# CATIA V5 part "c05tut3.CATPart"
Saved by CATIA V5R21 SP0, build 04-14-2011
Part number: Part1
Bounding box of the stored display mesh (mm): x -75 to 75, y -150 to 150, z 30 to 180
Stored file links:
  D:\CATIA V5R21 E-RESOURCES\CATIA-V5R21\catia-v5r21-prt\c05-catia-v5r20-prt\catia-v5r21-tut-03.CATPart
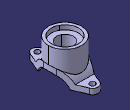
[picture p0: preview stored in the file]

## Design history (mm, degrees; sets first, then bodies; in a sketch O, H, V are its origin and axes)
Body1 (main body)
  Sketch1 on yz-plane, origin (0, 0, 0), H (0, 1, 0), V (0, 0, 1)
    point P1 (0, 42.5)
    line L1 (150, 55) -> (150, 30)
    line L2 (150, 30) -> (74.162, 30)
    line L3 (-150, 30) -> (-150, 55)
    line L4 (-150, 55) -> (-89.4427, 55)
    point P3 (150, 30)
    point P4 (-150, 30)
    arc A1 centre (0, 0) radius 80 from (74.162, 30) to (-74.162, 30) ccw
    point P7 (-74.162, 30)
    point P8 (0, 30)
    arc A2 centre (0, 0) radius 105 from (89.4427, 55) to (-89.4427, 55) ccw
    point P9 (89.4427, 55)
    line L5 (-74.162, 30) -> (-150, 30)
    line L6 (89.4427, 55) -> (150, 55)
    length L1 = 25
    distance H L2 = 30
    radius A1 = 80
    distance L3 L1 = 300
    radius A2 = 105
    coincidence: P1 V, P7 L2, P9 L4, L2 P8, L2 L5
    vertical: L1 V, L3 V
    horizontal: L2 H, L4 H, L5 H, L6 H
    equidistance: L1 L3 P1, L2 L4 P1, P3 P4 P8
  Pad1: profile Sketch1, direction (1, 0, 0), length 75, mirrored extent
  Sketch2 on xy-plane, origin (0, 0, 0), H (1, 0, 0), V (0, 1, 0)
    arc A1 centre (0, 0) radius 75 from (-68.7386, 30) to (-68.7386, -30) ccw
    point P1 (75, 0)
    arc A2 centre (0, 125) radius 25 from (22.9129, 135) to (-22.9129, 135) ccw
    point P2 (0, 125)
    point P3 (0, 150)
    arc A3 centre (0, -125) radius 25 from (-22.9129, -135) to (22.9129, -135) ccw
    point P4 (0, -125)
    point P5 (0, -150)
    reference projected line E1 (75, 89.4427) -> (75, -89.4427) from edge [face of Pad1 from Sketch1.A2 | end face of Pad1]
    reference projected line E2 (-75, 150) -> (75, 150) from edge [face of Pad1 from Sketch1.L6 | face of Pad1 from Sketch1.L1]
    reference projected line E3 (-75, -150) -> (75, -150) from edge [face of Pad1 from Sketch1.L3 | face of Pad1 from Sketch1.L4]
    line L1 (-22.9129, 135) -> (-68.7386, 30)
    line L2 (22.9129, 135) -> (68.7386, 30)
    line L3 (-68.7386, -30) -> (-22.9129, -135)
    line L4 (68.7386, -30) -> (22.9129, -135)
    point P12 (68.7386, -30)
    arc A4 centre (0, 0) radius 75 from (68.7386, -30) to (68.7386, 30) ccw
    radius A2 = 25
    radius A3 = 25
    coincidence: A1 P1, P1 H, P2 V, A2 P3, P3 V, P4 V, A3 P5, P5 V, A1 P12, A1 A4
    tangency: E1 A1, A2 E2, A3 E3, L1 A2, L1 A1, L2 A2, L2 A1, L3 A1, L3 A3, L4 A1, L4 A3
  Pocket1: profile Sketch2, direction (0, 0, 1), through (limit type 3), outer side
  Plane1: type Offset, RefPlane xy-plane, Offset 180
  Sketch3 on Plane1, origin (0, 0, 180), H (1, 0, 0), V (0, 1, 0)
    circle A1 centre (0, 0) radius 75
    radius A1 = 75
  Pad2: profile Sketch3, direction (0, 0, -1), up to face of Pad1 from Sketch1.A2
  Sketch4 on yz-plane, origin (0, 0, 0), H (0, 1, 0), V (0, 0, 1)
    line L1 (0, 0) -> (0, 180)
    line L2 (0, 180) -> (61.5, 180)
    line L3 (61.5, 180) -> (61.5, 160)
    line L4 (61.5, 160) -> (37.5, 160)
    line L5 (37.5, 160) -> (37.5, 0)
    point P5 (37.5, 0)
    line L6 (37.5, 0) -> (0, 0)
    reference projected line E1 (-75, 180) -> (75, 180) from edge [face of Pad2 from Sketch3.A1 | start face of Pad2]
    axis line L7 (0, 214.9745) -> (0, -17.6606)
    point P6 (0, 214.9745)
    length L3 = 20
    "Radius" L7 L5 = 37.5
    "Radius" L7 L3 = 61.5
    vertical: L1 V, L3 V, L5 V, L7 V
    horizontal: L2 H, L4 H, L6 H
    coincidence: P5 H, L2 E1, P6 V
  Groove1: profile Sketch4, axis Sketch4.L7, angle 360
  Sketch5 on face of Pad1 from Sketch1.L6, origin (0, 0, 55), H (1, 0, 0), V (0, 1, 0)
    circle A1 centre (0, 125) radius 12.5
    point P1 (0, 125)
    reference projected arc E1 centre (0, 125) radius 25 from (22.9129, 135) to (-22.9129, 135) ccw from edge [face of Pad1 from Sketch1.L6 | face of Pocket1]
    circle A2 centre (0, -125) radius 12.5
    radius A1 = 12.5
    concentricity: P1 E1
    symmetry: A1 A2 H
  Pocket2: profile Sketch5, direction (0, 0, -1), through (limit type 3)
